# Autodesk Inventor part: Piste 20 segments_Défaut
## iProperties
Shininess: 64.0
Length Units: 11269
Angle Units: 11279
Time Units: 11290
Mass Units: 11283
Length Display Precision: 3
Angle Display Precision: 2
Compacted: True
Part Number: Piste 20 segments_Défaut
Document SubType Name: Modeling
Created: 2006-01
Material: Par défaut
Designer: riri
Density: 0.0
Volumn: 0.0
Area: 0.0
PropertySet Name: Model Information
Control State: 0
Master: False
Checked Out: False
Author: riri
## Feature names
1. Extrusion1
2. Réseau circulaire1 [Circular Pattern]
3. Base1
